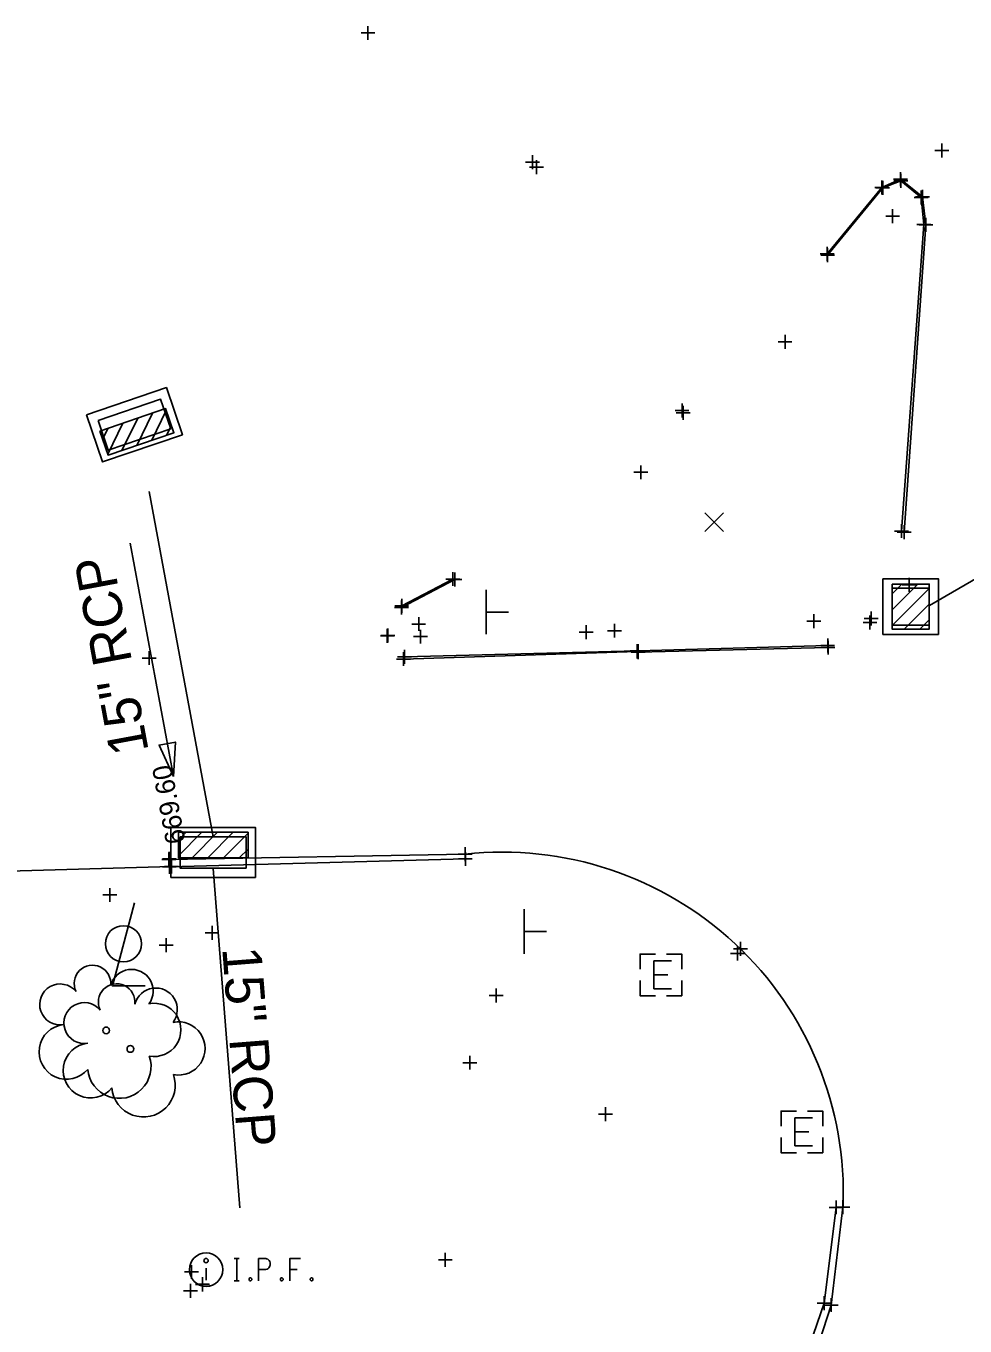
# Model space of a CAD drawing. Extents: x 2188719 to 2189819, y 654569 to 659504.
# Drawn here: x 2189283 to 2189350.5, y 655564.6 to 655658.1 of the extents above; entities that cross this region are included whole.
import ezdxf

# ---------------------------------------------------------------- set-up
doc = ezdxf.new("R2010")
doc.units = 0
for name, color, linetype in [('DR_X_Cells', 7, 'Continuous'), ('DR_X_Elev_Flow', 7, 'Continuous'), ('DR_X_Storm_Sewer', 7, 'Continuous'), ('DR_X_Text', 7, 'Continuous'), ('GK_Drainage_Nodes', 7, 'Continuous'), ('LT_X_Poles', 7, 'Continuous'), ('PV_X_Curb', 7, 'Continuous'), ('PV_X_EOP', 7, 'Continuous'), ('RD_X_Concrete_Pad', 7, 'Continuous'), ('SC_Scratch1', 7, 'Continuous'), ('SN_X_Public', 7, 'Continuous'), ('SV_X_Mon_Cells_Found', 7, 'Continuous'), ('SV_X_Random_Point', 7, 'Continuous'), ('SV_X_Shot_Marker', 7, 'Continuous'), ('UT_X_Electric_Cells', 7, 'Continuous'), ('VG_X_Cells', 7, 'Continuous')]:
    doc.layers.add(name, color=color, linetype=linetype)

msp = doc.modelspace()

# ---------------------------------------------------------------- linework, layer by layer
at = {"layer": 'DR_X_Cells'}
for p, q in [((2189290.982, 655627.93), (2189292.123, 655630.254)), ((2189292.052, 655628.293), (2189293.103, 655630.435)), ((2189288.524, 655628.37), (2189288.914, 655629.164)), ((2189288.889, 655627.297), (2189289.984, 655629.527)), ((2189289.912, 655627.566), (2189291.053, 655629.89)), ((2189293.121, 655628.657), (2189293.468, 655629.362)), ((2189345.305, 655616.119), (2189347.141, 655617.956)), ((2189345.305, 655617.251), (2189346.01, 655617.956)), ((2189345.305, 655614.988), (2189347.971, 655617.655)), ((2189346.175, 655614.727), (2189347.971, 655616.523)), ((2189347.306, 655614.727), (2189347.971, 655615.392)), ((2189294.535, 655600.124), (2189293.98, 655599.568)), ((2189295.665, 655600.124), (2189293.98, 655598.435)), ((2189296.795, 655600.124), (2189294.966, 655598.291)), ((2189297.924, 655600.124), (2189296.096, 655598.291)), ((2189298.98, 655600.05), (2189297.226, 655598.291)), ((2189298.98, 655598.917), (2189298.356, 655598.291))]:
    msp.add_line(p, q, dxfattribs=at)
for points in [[(2189287.354, 655630.131), (2189293.114, 655632.088), (2189294.267, 655628.694), (2189288.507, 655626.737)], [(2189288.2, 655629.713), (2189292.697, 655631.241), (2189293.421, 655629.111), (2189288.924, 655627.583)], [(2189288.323, 655628.963), (2189293.057, 655630.571), (2189293.647, 655628.835), (2189288.913, 655627.227)], [(2189344.638, 655618.342), (2189348.638, 655618.342), (2189348.638, 655614.342), (2189344.638, 655614.342)], [(2189345.305, 655617.956), (2189347.971, 655617.956), (2189347.971, 655614.727), (2189345.305, 655614.727)], [(2189345.305, 655617.675), (2189347.971, 655617.675), (2189347.971, 655615.009), (2189345.305, 655615.009)], [(2189299.522, 655596.874), (2189293.438, 655596.874), (2189293.438, 655600.458), (2189299.522, 655600.458)], [(2189298.98, 655598.291), (2189293.98, 655598.291), (2189293.98, 655600.124), (2189298.98, 655600.124)], [(2189298.855, 655597.541), (2189294.105, 655597.541), (2189294.105, 655599.791), (2189298.855, 655599.791)]]:
    msp.add_lwpolyline(points, close=True, dxfattribs=at)
at = {"layer": 'DR_X_Elev_Flow'}
for p, q in [((2189295.893, 655592.893), (2189296.893, 655592.893)), ((2189296.393, 655593.393), (2189296.393, 655592.393)), ((2189296.393, 655592.893), (2189296.393, 655592.893))]:
    msp.add_line(p, q, dxfattribs=at)
at = {"layer": 'DR_X_Storm_Sewer'}
for p, q in [((2189371.314, 655630.005), (2189348.002, 655616.423)), ((2189291.865, 655624.622), (2189296.48, 655599.791)), ((2189296.485, 655597.519), (2189298.384, 655573.128))]:
    msp.add_line(p, q, dxfattribs=at)
at = {"layer": 'DR_X_Text'}
msp.add_line((2189290.497, 655620.901), (2189293.613, 655604.137), dxfattribs=at)
msp.add_lwpolyline([(2189293.613, 655604.137), (2189292.584, 655606.387), (2189293.764, 655606.606)], close=True, dxfattribs=at)
at = {"layer": 'GK_Drainage_Nodes'}
for p, q in [((2189290.234, 655631.108), (2189290.234, 655631.108)), ((2189290.449, 655630.477), (2189290.449, 655630.477)), ((2189293.059, 655630.176), (2189293.059, 655630.176)), ((2189290.69, 655629.767), (2189290.69, 655629.767)), ((2189290.69, 655629.767), (2189290.69, 655629.767)), ((2189290.811, 655629.412), (2189290.811, 655629.412)), ((2189288.562, 655628.648), (2189288.562, 655628.648)), ((2189291.173, 655628.347), (2189291.173, 655628.347)), ((2189291.387, 655627.716), (2189291.387, 655627.716)), ((2189346.638, 655618.342), (2189346.638, 655618.342)), ((2189346.638, 655617.675), (2189346.638, 655617.675)), ((2189345.305, 655616.342), (2189345.305, 655616.342)), ((2189346.638, 655616.342), (2189346.638, 655616.342)), ((2189346.638, 655616.342), (2189346.638, 655616.342)), ((2189347.971, 655616.342), (2189347.971, 655616.342)), ((2189346.638, 655615.009), (2189346.638, 655615.009)), ((2189346.638, 655614.727), (2189346.638, 655614.727)), ((2189346.638, 655614.342), (2189346.638, 655614.342)), ((2189296.48, 655600.458), (2189296.48, 655600.458)), ((2189296.48, 655599.791), (2189296.48, 655599.791)), ((2189294.105, 655598.666), (2189294.105, 655598.666)), ((2189296.48, 655598.666), (2189296.48, 655598.666)), ((2189298.855, 655598.666), (2189298.855, 655598.666)), ((2189296.48, 655598.291), (2189296.48, 655598.291)), ((2189296.48, 655598.291), (2189296.48, 655598.291)), ((2189296.48, 655597.541), (2189296.48, 655597.541)), ((2189296.48, 655596.874), (2189296.48, 655596.874))]:
    msp.add_line(p, q, dxfattribs=at)
at = {"layer": 'LT_X_Poles'}
msp.add_lwpolyline([(2189290.808, 655595.064), (2189289.233, 655589.079), (2189291.596, 655589.079)], dxfattribs=at)
msp.add_circle((2189290.021, 655592.111), 1.3, dxfattribs=at)
at = {"layer": 'PV_X_Curb'}
for p, q in [((2189277.183, 655597.196), (2189293.484, 655597.659)), ((2189293.323, 655597.628), (2189314.611, 655598.205)), ((2189341.279, 655573.167), (2189340.412, 655566.28)), ((2189340.412, 655566.28), (2189339.07, 655562.363))]:
    msp.add_line(p, q, dxfattribs=at)
at = {"layer": 'PV_X_EOP'}
for p, q in [((2189345.911, 655647.06), (2189344.567, 655646.463)), ((2189347.489, 655645.793), (2189345.911, 655647.06)), ((2189344.567, 655646.463), (2189340.633, 655641.688)), ((2189347.74, 655643.784), (2189347.489, 655645.793)), ((2189346.166, 655621.698), (2189347.74, 655643.784)), ((2189313.716, 655618.325), (2189310.032, 655616.401)), ((2189327.034, 655613.067), (2189340.695, 655613.392)), ((2189310.169, 655612.576), (2189326.979, 655613.105)), ((2189293.289, 655598.164), (2189314.598, 655598.551)), ((2189341.77, 655573.178), (2189340.93, 655566.146)), ((2189340.93, 655566.146), (2189339.594, 655562.109))]:
    msp.add_line(p, q, dxfattribs=at)
msp.add_arc((2189317.286, 655574.192), 24.507, 357.62745, 96.29662, dxfattribs=at)
at = {"layer": 'RD_X_Concrete_Pad'}
for p, q in [((2189345.925, 655646.95), (2189344.624, 655646.437)), ((2189347.384, 655645.746), (2189345.925, 655646.95)), ((2189344.624, 655646.437), (2189340.665, 655641.593)), ((2189347.592, 655643.796), (2189347.384, 655645.746)), ((2189345.975, 655621.774), (2189347.592, 655643.796)), ((2189313.862, 655618.288), (2189310.016, 655616.28)), ((2189327.041, 655613.154), (2189340.671, 655613.539)), ((2189310.241, 655612.741), (2189326.967, 655613.152))]:
    msp.add_line(p, q, dxfattribs=at)
at = {"layer": 'SN_X_Public'}
for p, q in [((2189316.107, 655614.352), (2189316.107, 655617.552)), ((2189316.107, 655615.952), (2189317.707, 655615.952)), ((2189318.85, 655591.39), (2189318.85, 655594.59)), ((2189318.85, 655592.99), (2189320.45, 655592.99))]:
    msp.add_line(p, q, dxfattribs=at)
at = {"layer": 'SV_X_Mon_Cells_Found'}
msp.add_line((2189295.964, 655568.806), (2189295.964, 655567.922), dxfattribs=at)
for points in [[(2189297.994, 655569.489), (2189298.347, 655569.489)], [(2189298.171, 655567.889), (2189298.171, 655569.489)], [(2189299.736, 655567.889), (2189299.736, 655569.489), (2189300.265, 655569.489), (2189300.32, 655569.476), (2189300.397, 655569.451), (2189300.431, 655569.426), (2189300.463, 655569.401), (2189300.508, 655569.338), (2189300.541, 655569.275), (2189300.563, 655569.174), (2189300.563, 655569.023), (2189300.552, 655568.972), (2189300.53, 655568.897), (2189300.486, 655568.809), (2189300.441, 655568.771), (2189300.408, 655568.746), (2189300.353, 655568.72), (2189300.265, 655568.708), (2189299.736, 655568.708)], [(2189302.745, 655569.489), (2189301.985, 655569.489), (2189301.985, 655567.889)], [(2189301.985, 655568.708), (2189302.525, 655568.708)], [(2189297.994, 655567.889), (2189298.347, 655567.889)], [(2189299.13, 655568.103), (2189299.185, 655568.103), (2189299.218, 655568.078), (2189299.251, 655568.028), (2189299.251, 655567.965), (2189299.218, 655567.914), (2189299.185, 655567.889), (2189299.13, 655567.889), (2189299.097, 655567.914), (2189299.064, 655567.965), (2189299.064, 655568.028), (2189299.097, 655568.078), (2189299.13, 655568.103)], [(2189301.378, 655568.103), (2189301.434, 655568.103), (2189301.467, 655568.078), (2189301.5, 655568.028), (2189301.5, 655567.965), (2189301.467, 655567.914), (2189301.434, 655567.889), (2189301.378, 655567.889), (2189301.345, 655567.914), (2189301.312, 655567.965), (2189301.312, 655568.028), (2189301.345, 655568.078), (2189301.378, 655568.103)], [(2189303.528, 655568.103), (2189303.583, 655568.103), (2189303.616, 655568.078), (2189303.649, 655568.028), (2189303.649, 655567.965), (2189303.616, 655567.914), (2189303.583, 655567.889), (2189303.528, 655567.889), (2189303.495, 655567.914), (2189303.462, 655567.965), (2189303.462, 655568.028), (2189303.495, 655568.078), (2189303.528, 655568.103)]]:
    msp.add_lwpolyline(points, dxfattribs=at)
for centre, radius in [((2189295.964, 655568.689), 1.2), ((2189295.964, 655569.341), 0.16)]:
    msp.add_circle(centre, radius, dxfattribs=at)
at = {"layer": 'SV_X_Random_Point'}
for p, q in [((2189331.841, 655621.742), (2189333.175, 655623.076)), ((2189331.841, 655623.076), (2189333.175, 655621.742))]:
    msp.add_line(p, q, dxfattribs=at)
at = {"layer": 'SV_X_Shot_Marker'}
for p, q in [((2189307.107, 655657.571), (2189308.107, 655657.571)), ((2189307.607, 655658.071), (2189307.607, 655657.071)), ((2189307.607, 655657.571), (2189307.607, 655657.571)), ((2189348.386, 655649.12), (2189349.386, 655649.12)), ((2189348.886, 655649.62), (2189348.886, 655648.62)), ((2189348.886, 655649.12), (2189348.886, 655649.12)), ((2189318.946, 655648.277), (2189319.946, 655648.277)), ((2189319.235, 655647.918), (2189320.235, 655647.918)), ((2189319.446, 655648.777), (2189319.446, 655647.777)), ((2189319.446, 655648.277), (2189319.446, 655648.277)), ((2189319.735, 655648.418), (2189319.735, 655647.418)), ((2189319.735, 655647.918), (2189319.735, 655647.918)), ((2189344.567, 655646.963), (2189344.567, 655645.963)), ((2189344.624, 655646.937), (2189344.624, 655645.937)), ((2189345.411, 655647.06), (2189346.411, 655647.06)), ((2189345.425, 655646.95), (2189346.425, 655646.95)), ((2189345.911, 655647.56), (2189345.911, 655646.56)), ((2189345.911, 655647.06), (2189345.911, 655647.06)), ((2189345.925, 655647.45), (2189345.925, 655646.45)), ((2189345.925, 655646.95), (2189345.925, 655646.95)), ((2189344.067, 655646.463), (2189345.067, 655646.463)), ((2189344.124, 655646.437), (2189345.124, 655646.437)), ((2189344.567, 655646.463), (2189344.567, 655646.463)), ((2189344.624, 655646.437), (2189344.624, 655646.437)), ((2189347.384, 655646.246), (2189347.384, 655645.246)), ((2189347.489, 655646.293), (2189347.489, 655645.293)), ((2189346.884, 655645.746), (2189347.884, 655645.746)), ((2189346.989, 655645.793), (2189347.989, 655645.793)), ((2189347.384, 655645.746), (2189347.384, 655645.746)), ((2189347.489, 655645.793), (2189347.489, 655645.793)), ((2189344.842, 655644.4), (2189345.842, 655644.4)), ((2189345.342, 655644.9), (2189345.342, 655643.9)), ((2189345.342, 655644.4), (2189345.342, 655644.4)), ((2189347.592, 655644.296), (2189347.592, 655643.296)), ((2189347.74, 655644.284), (2189347.74, 655643.284)), ((2189347.092, 655643.796), (2189348.092, 655643.796)), ((2189347.24, 655643.784), (2189348.24, 655643.784)), ((2189347.592, 655643.796), (2189347.592, 655643.796)), ((2189347.74, 655643.784), (2189347.74, 655643.784)), ((2189340.133, 655641.688), (2189341.133, 655641.688)), ((2189340.165, 655641.593), (2189341.165, 655641.593)), ((2189340.633, 655642.188), (2189340.633, 655641.188)), ((2189340.633, 655641.688), (2189340.633, 655641.688)), ((2189340.665, 655642.093), (2189340.665, 655641.093)), ((2189340.665, 655641.593), (2189340.665, 655641.593)), ((2189337.603, 655635.874), (2189337.603, 655634.874)), ((2189337.103, 655635.374), (2189338.103, 655635.374)), ((2189337.603, 655635.374), (2189337.603, 655635.374)), ((2189329.695, 655630.442), (2189330.695, 655630.442)), ((2189329.782, 655630.274), (2189330.782, 655630.274)), ((2189330.195, 655630.942), (2189330.195, 655629.942)), ((2189330.195, 655630.442), (2189330.195, 655630.442)), ((2189330.282, 655630.774), (2189330.282, 655629.774)), ((2189330.282, 655630.274), (2189330.282, 655630.274)), ((2189327.229, 655626.494), (2189327.229, 655625.494)), ((2189326.729, 655625.994), (2189327.729, 655625.994)), ((2189327.229, 655625.994), (2189327.229, 655625.994)), ((2189345.475, 655621.774), (2189346.475, 655621.774)), ((2189345.666, 655621.698), (2189346.666, 655621.698)), ((2189345.975, 655622.274), (2189345.975, 655621.274)), ((2189345.975, 655621.774), (2189345.975, 655621.774)), ((2189346.166, 655622.198), (2189346.166, 655621.198)), ((2189346.166, 655621.698), (2189346.166, 655621.698)), ((2189313.216, 655618.325), (2189314.216, 655618.325)), ((2189313.362, 655618.288), (2189314.362, 655618.288)), ((2189313.716, 655618.825), (2189313.716, 655617.825)), ((2189313.716, 655618.325), (2189313.716, 655618.325)), ((2189313.862, 655618.788), (2189313.862, 655617.788)), ((2189313.862, 655618.288), (2189313.862, 655618.288)), ((2189346.536, 655618.413), (2189346.536, 655617.413)), ((2189346.036, 655617.913), (2189347.036, 655617.913)), ((2189346.536, 655617.913), (2189346.536, 655617.913)), ((2189309.516, 655616.28), (2189310.516, 655616.28)), ((2189309.532, 655616.401), (2189310.532, 655616.401)), ((2189310.016, 655616.78), (2189310.016, 655615.78)), ((2189310.016, 655616.28), (2189310.016, 655616.28)), ((2189310.032, 655616.901), (2189310.032, 655615.901)), ((2189310.032, 655616.401), (2189310.032, 655616.401)), ((2189311.254, 655615.592), (2189311.254, 655614.592)), ((2189339.176, 655615.292), (2189340.176, 655615.292)), ((2189339.676, 655615.792), (2189339.676, 655614.792)), ((2189339.676, 655615.292), (2189339.676, 655615.292)), ((2189343.21, 655615.196), (2189344.21, 655615.196)), ((2189343.295, 655615.496), (2189344.295, 655615.496)), ((2189343.71, 655615.696), (2189343.71, 655614.696)), ((2189343.71, 655615.196), (2189343.71, 655615.196)), ((2189343.795, 655615.996), (2189343.795, 655614.996)), ((2189343.795, 655615.496), (2189343.795, 655615.496)), ((2189308.498, 655614.233), (2189309.498, 655614.233)), ((2189308.543, 655614.265), (2189309.543, 655614.265)), ((2189308.998, 655614.733), (2189308.998, 655613.733)), ((2189308.998, 655614.233), (2189308.998, 655614.233)), ((2189309.043, 655614.765), (2189309.043, 655613.765)), ((2189309.043, 655614.265), (2189309.043, 655614.265)), ((2189310.754, 655615.092), (2189311.754, 655615.092)), ((2189311.254, 655615.092), (2189311.254, 655615.092)), ((2189311.387, 655614.682), (2189311.387, 655613.682)), ((2189322.795, 655614.501), (2189323.795, 655614.501)), ((2189323.295, 655615.001), (2189323.295, 655614.001)), ((2189323.295, 655614.501), (2189323.295, 655614.501)), ((2189324.836, 655614.611), (2189325.836, 655614.611)), ((2189325.336, 655615.111), (2189325.336, 655614.111)), ((2189325.336, 655614.611), (2189325.336, 655614.611)), ((2189310.887, 655614.182), (2189311.887, 655614.182)), ((2189311.387, 655614.182), (2189311.387, 655614.182)), ((2189326.967, 655613.652), (2189326.967, 655612.652)), ((2189326.979, 655613.605), (2189326.979, 655612.605)), ((2189327.034, 655613.567), (2189327.034, 655612.567)), ((2189327.041, 655613.654), (2189327.041, 655612.654)), ((2189340.171, 655613.539), (2189341.171, 655613.539)), ((2189340.195, 655613.392), (2189341.195, 655613.392)), ((2189340.671, 655614.039), (2189340.671, 655613.039)), ((2189340.671, 655613.539), (2189340.671, 655613.539)), ((2189340.695, 655613.892), (2189340.695, 655612.892)), ((2189340.695, 655613.392), (2189340.695, 655613.392)), ((2189291.374, 655612.647), (2189292.374, 655612.647)), ((2189291.874, 655613.147), (2189291.874, 655612.147)), ((2189291.874, 655612.647), (2189291.874, 655612.647)), ((2189309.669, 655612.576), (2189310.669, 655612.576)), ((2189309.741, 655612.741), (2189310.741, 655612.741)), ((2189310.169, 655613.076), (2189310.169, 655612.076)), ((2189310.169, 655612.576), (2189310.169, 655612.576)), ((2189310.241, 655613.241), (2189310.241, 655612.241)), ((2189310.241, 655612.741), (2189310.241, 655612.741)), ((2189326.467, 655613.152), (2189327.467, 655613.152)), ((2189326.479, 655613.105), (2189327.479, 655613.105)), ((2189326.534, 655613.067), (2189327.534, 655613.067)), ((2189326.541, 655613.154), (2189327.541, 655613.154)), ((2189326.967, 655613.152), (2189326.967, 655613.152)), ((2189326.979, 655613.105), (2189326.979, 655613.105)), ((2189327.034, 655613.067), (2189327.034, 655613.067)), ((2189327.041, 655613.154), (2189327.041, 655613.154)), ((2189293.289, 655598.664), (2189293.289, 655597.664)), ((2189293.32, 655598.716), (2189293.32, 655597.716)), ((2189314.098, 655598.551), (2189315.098, 655598.551)), ((2189314.598, 655599.051), (2189314.598, 655598.051)), ((2189314.598, 655598.551), (2189314.598, 655598.551)), ((2189314.611, 655598.705), (2189314.611, 655597.705)), ((2189292.789, 655598.164), (2189293.789, 655598.164)), ((2189292.82, 655598.216), (2189293.82, 655598.216)), ((2189292.823, 655597.628), (2189293.823, 655597.628)), ((2189292.984, 655597.659), (2189293.984, 655597.659)), ((2189293.289, 655598.164), (2189293.289, 655598.164)), ((2189293.32, 655598.216), (2189293.32, 655598.216)), ((2189293.323, 655598.128), (2189293.323, 655597.128)), ((2189293.323, 655597.628), (2189293.323, 655597.628)), ((2189293.484, 655598.159), (2189293.484, 655597.159)), ((2189293.484, 655597.659), (2189293.484, 655597.659)), ((2189314.111, 655598.205), (2189315.111, 655598.205)), ((2189314.611, 655598.205), (2189314.611, 655598.205)), ((2189288.537, 655595.617), (2189289.537, 655595.617)), ((2189289.037, 655596.117), (2189289.037, 655595.117)), ((2189289.037, 655595.617), (2189289.037, 655595.617)), ((2189292.597, 655592.016), (2189293.597, 655592.016)), ((2189293.097, 655592.516), (2189293.097, 655591.516)), ((2189293.097, 655592.016), (2189293.097, 655592.016)), ((2189334.178, 655591.905), (2189334.178, 655590.905)), ((2189334.391, 655592.241), (2189334.391, 655591.241)), ((2189333.678, 655591.405), (2189334.678, 655591.405)), ((2189333.891, 655591.741), (2189334.891, 655591.741)), ((2189334.178, 655591.405), (2189334.178, 655591.405)), ((2189334.391, 655591.741), (2189334.391, 655591.741)), ((2189316.319, 655588.395), (2189317.319, 655588.395)), ((2189316.819, 655588.895), (2189316.819, 655587.895)), ((2189316.819, 655588.395), (2189316.819, 655588.395)), ((2189314.437, 655583.564), (2189315.437, 655583.564)), ((2189314.937, 655584.064), (2189314.937, 655583.064)), ((2189314.937, 655583.564), (2189314.937, 655583.564)), ((2189324.193, 655579.858), (2189325.193, 655579.858)), ((2189324.693, 655580.358), (2189324.693, 655579.358)), ((2189324.693, 655579.858), (2189324.693, 655579.858)), ((2189340.779, 655573.167), (2189341.779, 655573.167)), ((2189341.27, 655573.178), (2189342.27, 655573.178)), ((2189341.279, 655573.667), (2189341.279, 655572.667)), ((2189341.279, 655573.167), (2189341.279, 655573.167)), ((2189341.77, 655573.678), (2189341.77, 655572.678)), ((2189341.77, 655573.178), (2189341.77, 655573.178)), ((2189312.671, 655569.401), (2189313.671, 655569.401)), ((2189313.171, 655569.901), (2189313.171, 655568.901)), ((2189313.171, 655569.401), (2189313.171, 655569.401)), ((2189294.412, 655568.523), (2189295.412, 655568.523)), ((2189294.412, 655568.523), (2189295.412, 655568.523)), ((2189294.912, 655569.023), (2189294.912, 655568.023)), ((2189294.912, 655569.023), (2189294.912, 655568.023)), ((2189294.912, 655568.523), (2189294.912, 655568.523)), ((2189294.912, 655568.523), (2189294.912, 655568.523)), ((2189294.839, 655567.671), (2189294.839, 655566.671)), ((2189295.197, 655567.639), (2189296.197, 655567.639)), ((2189295.2, 655567.63), (2189296.2, 655567.63)), ((2189295.697, 655568.139), (2189295.697, 655567.139)), ((2189295.697, 655567.639), (2189295.697, 655567.639)), ((2189295.7, 655568.13), (2189295.7, 655567.13)), ((2189295.7, 655567.63), (2189295.7, 655567.63)), ((2189294.339, 655567.171), (2189295.339, 655567.171)), ((2189294.839, 655567.171), (2189294.839, 655567.171)), ((2189340.412, 655566.78), (2189340.412, 655565.78)), ((2189340.93, 655566.646), (2189340.93, 655565.646)), ((2189339.912, 655566.28), (2189340.912, 655566.28)), ((2189340.412, 655566.28), (2189340.412, 655566.28)), ((2189340.43, 655566.146), (2189341.43, 655566.146)), ((2189340.93, 655566.146), (2189340.93, 655566.146))]:
    msp.add_line(p, q, dxfattribs=at)
at = {"layer": 'UT_X_Electric_Cells'}
for p, q in [((2189328.178, 655589.873), (2189329.178, 655589.873)), ((2189328.678, 655589.873), (2189328.678, 655589.873)), ((2189338.317, 655578.59), (2189339.317, 655578.59)), ((2189338.817, 655578.59), (2189338.817, 655578.59))]:
    msp.add_line(p, q, dxfattribs=at)
for points in [[(2189328.278, 655591.373), (2189327.178, 655591.373), (2189327.178, 655590.273)], [(2189329.428, 655590.873), (2189328.178, 655590.873), (2189328.178, 655588.873), (2189329.428, 655588.873)], [(2189330.178, 655590.273), (2189330.178, 655591.373), (2189329.078, 655591.373)], [(2189327.178, 655589.473), (2189327.178, 655588.373), (2189328.278, 655588.373)], [(2189329.078, 655588.373), (2189330.178, 655588.373), (2189330.178, 655589.473)], [(2189338.417, 655580.09), (2189337.317, 655580.09), (2189337.317, 655578.99)], [(2189340.317, 655578.99), (2189340.317, 655580.09), (2189339.217, 655580.09)], [(2189339.567, 655579.59), (2189338.317, 655579.59), (2189338.317, 655577.59), (2189339.567, 655577.59)], [(2189337.317, 655578.19), (2189337.317, 655577.09), (2189338.417, 655577.09)], [(2189339.217, 655577.09), (2189340.317, 655577.09), (2189340.317, 655578.19)]]:
    msp.add_lwpolyline(points, dxfattribs=at)
at = {"layer": 'VG_X_Cells'}
for centre in [(2189288.779, 655585.886), (2189290.518, 655584.548)]:
    msp.add_circle(centre, 0.24, dxfattribs=at)
for centre, radius, start, end in [((2189287.795, 655589.254), 1.317, 354.0047, 205.97412), ((2189290.605, 655588.715), 1.553, 323.82996, 165.0376), ((2189285.47, 655587.75), 1.471, 39.06254, 279.54124), ((2189289.534, 655587.916), 1.317, 354.0047, 205.97412), ((2189292.344, 655587.377), 1.553, 323.82996, 165.0376), ((2189287.209, 655586.412), 1.471, 39.06254, 279.54124), ((2189292.239, 655585.922), 1.915, 259.14531, 101.45961), ((2189285.926, 655584.338), 1.974, 96.17219, 320.57371), ((2189293.978, 655584.584), 1.915, 259.14531, 101.45961), ((2189287.665, 655583), 1.974, 96.17219, 320.57371), ((2189289.725, 655583.281), 2.284, 184.94757, 19.45715), ((2189291.464, 655581.943), 2.284, 184.94757, 19.45715)]:
    msp.add_arc(centre, radius, start, end, dxfattribs=at)

# ---------------------------------------------------------------- texts
at = {"layer": 'DR_X_Text'}
for rotation, p in [(100.52899, (2189291.848, 655605.968)), (274.45333, (2189297.122, 655591.79))]:
    msp.add_text('15" RCP', height=2.8, rotation=rotation, dxfattribs=at).set_placement(p)
at = {"layer": 'SC_Scratch1'}
msp.add_text('669.60', height=1.4, rotation=100.52899, dxfattribs=at).set_placement((2189294.489, 655599.421))

doc.saveas('drawing.dxf')
